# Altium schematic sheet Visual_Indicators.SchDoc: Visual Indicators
size A4; DocumentNumber: 12; SheetNumber: 12; SheetTotal: 12
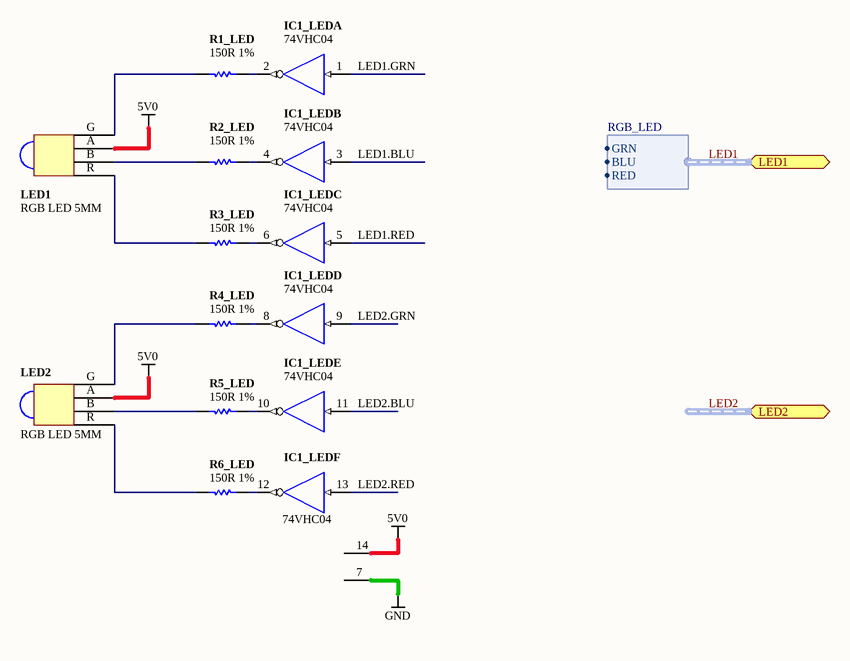
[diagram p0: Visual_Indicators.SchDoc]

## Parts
IC1_LED  74VHC04  [TSSOP14]  (parts A,B,C,D,E,F of 6)
LED1  RGB LED 5MM  [LED-RGB-5MM-RA]
LED2  RGB LED 5MM  [LED-RGB-5MM-RA]
R1_LED  150R 1%  [RESC1005-STAR]
R2_LED  150R 1%  [RESC1005-STAR]
R3_LED  150R 1%  [RESC1005-STAR]
R4_LED  150R 1%  [RESC1005-STAR]
R5_LED  150R 1%  [RESC1005-STAR]
R6_LED  150R 1%  [RESC1005-STAR]

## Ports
LED1 (harness RGB_LED), LED2 (harness RGB_LED)

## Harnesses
RGB_LED: GRN, BLU, RED

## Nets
5V0: IC1_LED.14(VCC) LED1.A LED2.A
GND: IC1_LED.7(GND)
LED1.BLU: IC1_LED.3(A)
LED1.GRN: IC1_LED.1(A)
LED1.RED: IC1_LED.5(A)
LED2.BLU: IC1_LED.11(A)
LED2.GRN: IC1_LED.9(A)
LED2.RED: IC1_LED.13(A)
NetIC1_LED_2: IC1_LED.2(Y) R1_LED.2
NetIC1_LED_4: IC1_LED.4(Y) R2_LED.2
NetIC1_LED_6: IC1_LED.6(Y) R3_LED.2
NetIC1_LED_8: IC1_LED.8(Y) R4_LED.2
NetIC1_LED_10: IC1_LED.10(Y) R5_LED.2
NetIC1_LED_12: IC1_LED.12(Y) R6_LED.2
NetLED1_B: LED1.B R2_LED.1
NetLED1_G: LED1.G R1_LED.1
NetLED1_R: LED1.R R3_LED.1
NetLED2_B: LED2.B R5_LED.1
NetLED2_G: LED2.G R4_LED.1
NetLED2_R: LED2.R R6_LED.1

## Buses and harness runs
harness LED1 = port LED1
harness LED2 = port LED2

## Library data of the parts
IC1_LED = D-205-0004: HEX Inverter
LED1 LED2 = D-153-0001: LED, RGB, 5mm, 540R2GBC-CA, Common Anode; Brightness: 1500 mcd; Peak Wave Length: nm
R1_LED R2_LED R3_LED R4_LED R5_LED R6_LED = D-100-0005: Resistor, 150R 1% 0402 (1005); Power Rating: 63 mW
